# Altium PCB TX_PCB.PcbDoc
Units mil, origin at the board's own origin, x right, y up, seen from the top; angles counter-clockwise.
Board outline 2335 x 1875 mil, 2 copper layers (Top Layer, Bottom Layer); 103 components, 81 nets, 424 pads, 0 vias.
Unrouted connection lines stored in the file: 259.
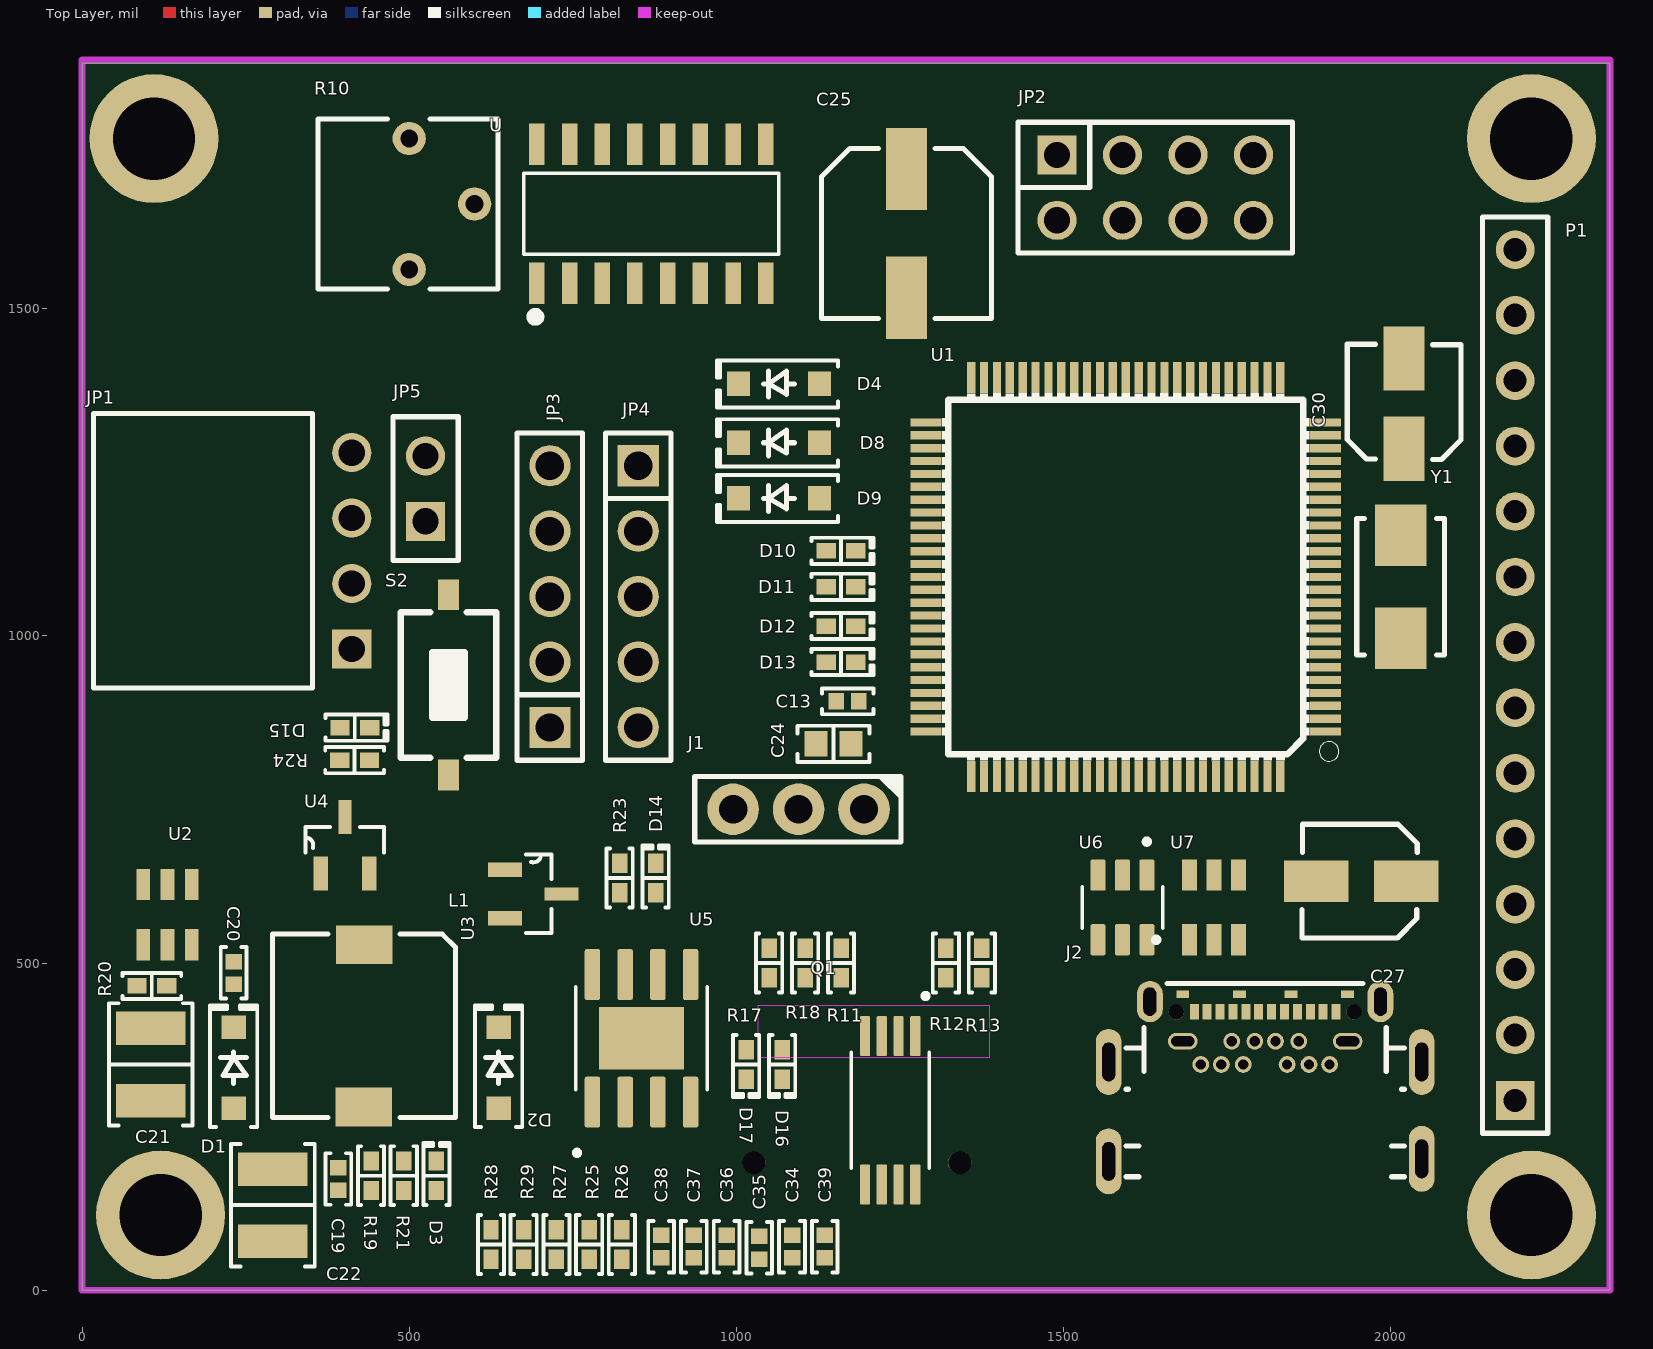
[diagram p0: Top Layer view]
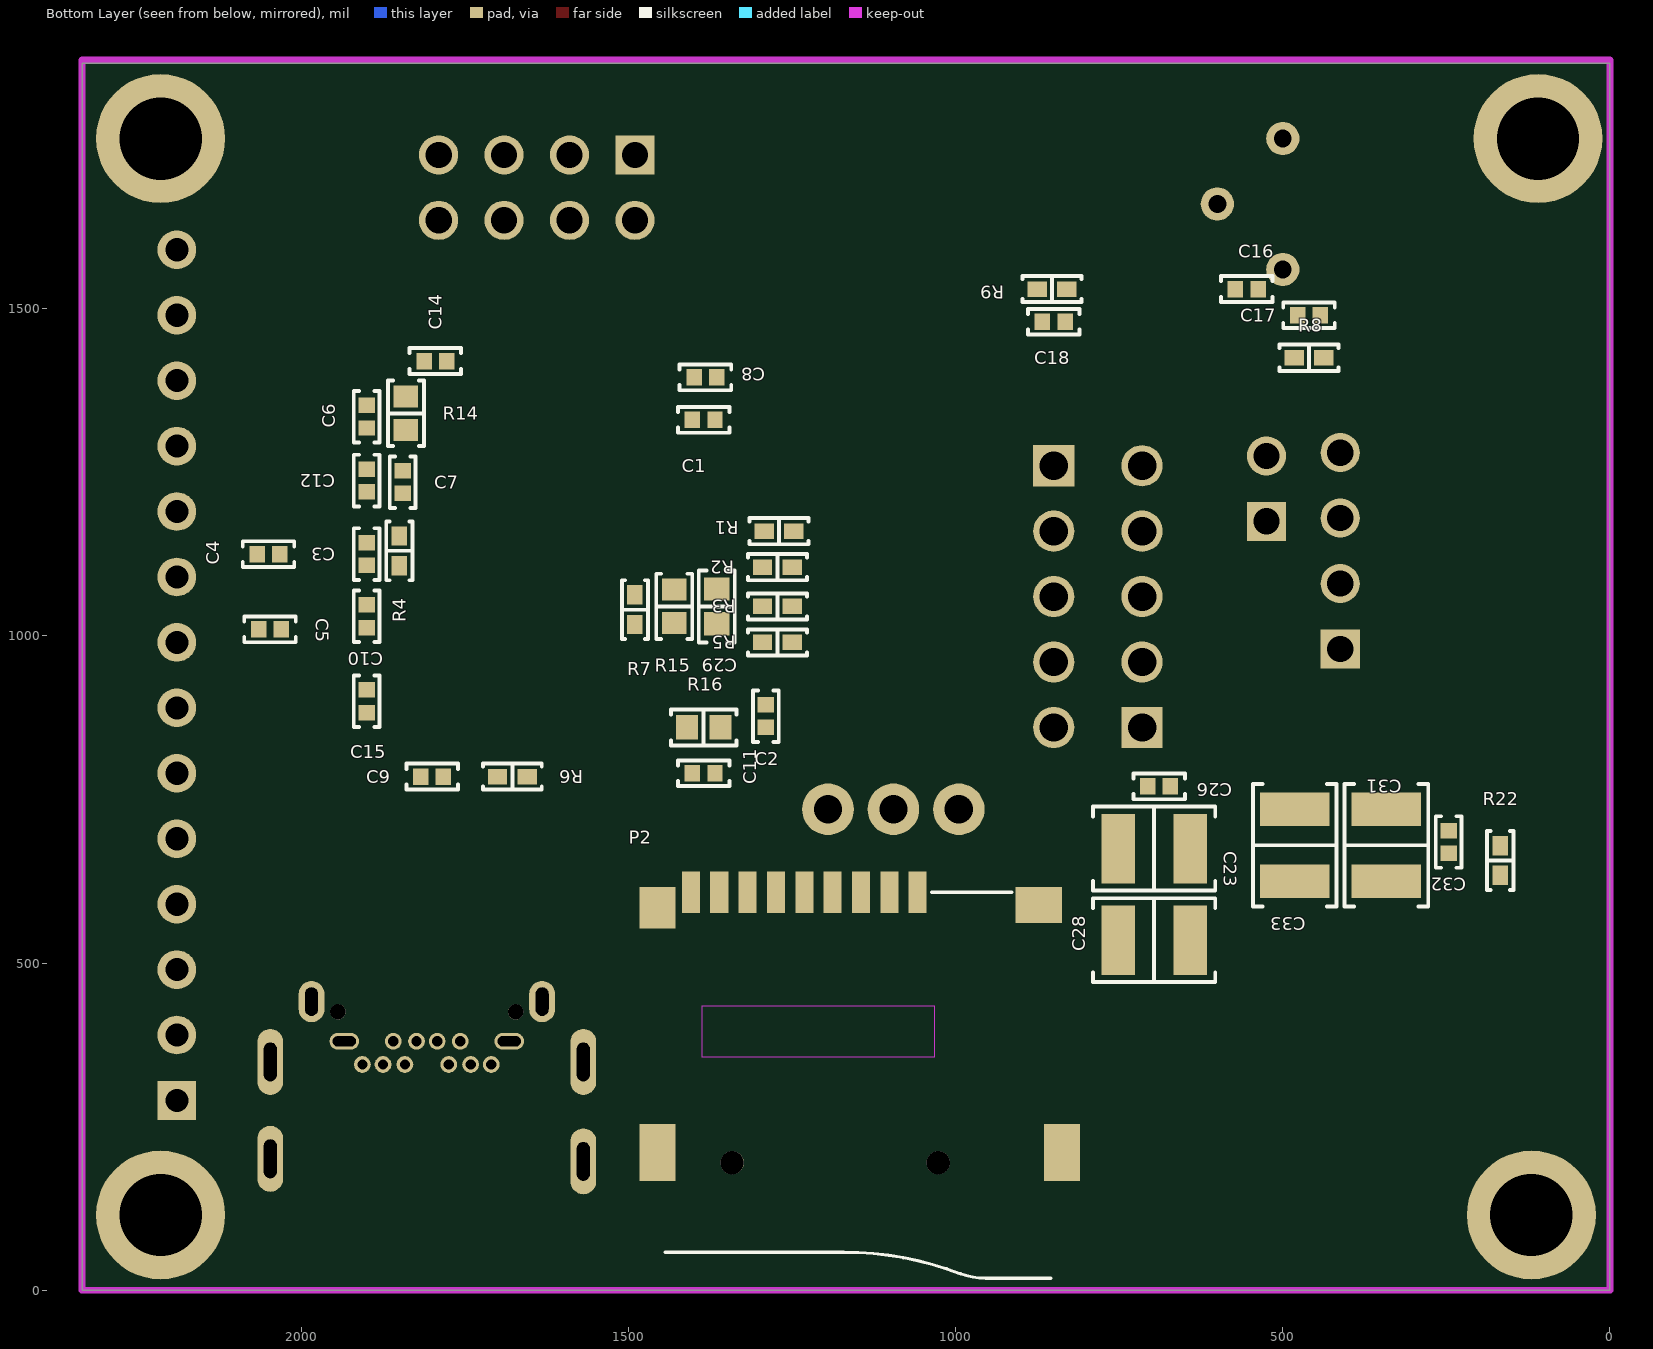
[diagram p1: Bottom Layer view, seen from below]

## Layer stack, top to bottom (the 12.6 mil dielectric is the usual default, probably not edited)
Top Solder: solder mask 0.4, Solder Resist, Dk 3.5
Top Layer: signal copper 1.4
Dielectric 1: dielectric 12.6, FR-4, Dk 4.8
Bottom Layer: signal copper 1.4
Bottom Solder: solder mask 0.4, Solder Resist, Dk 3.5

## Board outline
0,0 0,1875 2335,1875 2335,0

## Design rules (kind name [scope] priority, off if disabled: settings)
Clearance [All] p1: gap=5 ignorepadtopadclearanceinfootprint=FALSE
PolygonConnect [All] p1: connectstyle=Relief reliefconductorwidth=10 reliefentries=4 polygonreliefangle="90 Angle" airgapwidth=10
RoutingVias [All] p1: holewidth=28 width=50 viastyle="Through Hole" minholewidth=28 minwidth=50 maxholewidth=28 maxwidth=50
SolderMaskExpansion [All] p1: expansion=4 istentingtop=FALSE
Width [All] p1: maxlimit=10 minlimit=10 preferedwidth=10
30 further rules are at their usual default settings.

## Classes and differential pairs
component class USB_C: C34 C35 C36 C37 C38 C39 D16 D17 J2 Q1 R25 R26 R27 R28 R29 U5 U6 U7
component class Audio: C16 C17 C18 JP5 P2 R8 R9 R10 R11 R12 R13 R17 R18 U
component class Power_2: C19 C20 C21 C22 C23 C26 C28 C31 C32 C33 D1 D2 D3 D14 D15 L1 R19 R20 R21 R22 R23 R24 U2 U3 U4
component class MAIN_TX: "  " C1 C2 C3 C4 C5 C6 C7 C8 C9 C10 C11 C12 C13 C14 C15 C24 C25 C27 C29 C30 D4 D8 D9 D10 D11 D12 D13 J1 JP1 JP2 JP3 JP4 P1 R1 R2 R3 R4 R5 R6 R7 R14 R15 R16 S2 U1 Y1

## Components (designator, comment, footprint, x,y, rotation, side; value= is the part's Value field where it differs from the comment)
C1 "2.2 µF" "CAP 0402_1005" 1385,1330 r180 bottom
C2 "2.2 µF" "CAP 0402_1005" 1290,877.32 r90 bottom
C3 "0.1 µF" "CAP 0402_1005" 1900,1125 r270 bottom
C4 "20 pF" "CAP 0402_1005" 2050,1125 r180 bottom
C5 "20 pF" "CAP 0402_1005" 2047.68,1010 r180 bottom
C6 "0.1 µF" "CAP 0402_1005" 1900,1335 r270 bottom
C7 "0.1 µF" "CAP 0402_1005" 1845,1235 r270 bottom
C8 "0.1 µF" "CAP 0402_1005" 1382.32,1395 r180 bottom
C9 "0.1 µF" "CAP 0402_1005" 1800,785 r0 bottom
C10 "0.1 µF" "CAP 0402_1005" 1900,1030 r90 bottom
C11 "0.1 µF" "CAP 0402_1005" 1385,790 r180 bottom
C12 "0.1 µF" "CAP 0402_1005" 1900,1237.32 r270 bottom
C13 "0.1 µF" "CAP 0402_1005" 1170,900 r0 top
C14 "0.1 µF" "CAP 0402_1005" 1795,1420 r180 bottom
C15 "1 µF" "CAP 0402_1005" 1900,900 r90 bottom
C16 "0.22 µF" "CAP 0402_1005" 555,1530 r0 bottom
C17 "0.1 µF" "CAP 0402_1005" 460,1490 r180 bottom
C18 "1 µF" "CAP 0402_1005" 850,1480 r0 bottom
C19 "1000 pF" "CAP 0402_1005" 391.66,170 r90 top
C20 "0.1 µF" "CAP 0402_1005" 231.66,485 r270 top
C21 "10 µF" "CAP 1210_3225 - 1MM" 105,345 r90 top
C22 "22 µF" "CAP 1210_3225 - 1MM" 291.66,130 r90 top
C23 "10 µF" "CAP 1210_3225 - 1MM" 696.66,675 r0 bottom
C24 "0.1 µF" "CAP 0603_1608" 1148.43,835 r180 top
C25 "220 µF" "CAP ALSMD 6.6MM H6.1MM" 1260,1615 r270 top
C26 "0.1µF" "CAP 0402_1005" 688.98,770 r0 bottom
C27 "1 µF" "CAP ALSMD 4.3MM H5.4MM" 1955,625 r180 top
C28 "10 µF" "CAP 1210_3225 - 1MM" 696.66,535 r180 bottom
C29 "0.1 µF" "CAP 0603_1608" 1365,1045 r270 bottom
C30 "1 µF" "CAP ALSMD 4.3MM H5.4MM" 2020,1355 r90 top
C31 "10 µF" "CAP 1210_3225 - 1MM" 341.66,680 r90 bottom
C32 "0.1µF" "CAP 0402_1005" 246.66,685 r90 bottom
C33 "10 µF" "CAP 1210_3225 - 1MM" 481.66,680 r270 bottom
C34 "0.1 µF" "CAP 0402_1005" 1085,66.66 r90 top
C35 "0.1 µF" "CAP 0402_1005" 1035,65 r90 top
C36 "0.1 µF" "CAP 0402_1005" 985,66.66 r90 top
C37 "0.1 µF" "CAP 0402_1005" 935,66.66 r90 top
C38 "10 µF" "CAP 0402_1005" 885,66.66 r90 top
C39 "0.1 µF" "CAP 0402_1005" 1135,66.66 r90 top
D1 "1N5819HW-7-F" SOD-123 231.66,340 r90 top
D2 "1N5819HW-7-F" SOD-123 636.66,340 r90 top
D3 "Green" "LED 0402_1005 GREEN" 541.66,175 r90 top
D4 "1N5819HW-7-F" SOD-123 1065,1385 r180 top
D8 "1N5819HW-7-F" SOD-123 1065,1295 r180 top
D9 "1N5819HW-7-F" SOD-123 1065,1210 r180 top
D10 "Red" "LED 0402_1005 RED" 1160,1130 r0 top
D11 "Yellow" "LED 0402_1005 YELLOW" 1160,1075 r0 top
D12 "Green" "LED 0402_1005 GREEN" 1160,1015 r0 top
D13 "Blue" "LED 0402_1005 BLUE" 1160,960 r0 top
D14 "Yellow" "LED 0402_1005 YELLOW" 876.66,630 r90 top
D15 "Red" "LED 0402_1005 RED" 416.87,859.76 r0 top
D16 "Green" "LED 0402_1005 GREEN" 1070,345 r270 top
D17 "Red" "LED 0402_1005 RED" 1015,345 r270 top
J1 "M20-7820342" "HARWIN M20-7820345" 1095,735 r270 top
J2 "2129691-1" "TE USB-C 2129691-1" 1808.07,248.15 r180 top
JP1 "JP 1x4 2.54" "JP 1x4 CC" 412.32,1130 r90 top
JP2 "JP 2x4 2.54" "JP 2x4 CT" 1640,1685 r0 top
JP3 "JP 1x5 2.54" "JP 1x5 DT" 715,860 r90 top
JP4 "JP 1x5 2.54" "JP 1x5 DT" 850,1260 r270 top
JP5 "JP 1x2 2.54" "JP 1x2 CT" 525,1175 r90 top
L1 "10µH" "TDK SLF7032" 430.93,403.98 r270 top
P1 "Header 14" HDR1X14 2190,290 r90 top
P2 "ST-TF-003A" SUNTECH_ST-TF-003A 1196.61,398.39 r180 bottom
Q1 "FS8205A" SOP65P640X120-8N 1235,275 r270 top
R1 "680 Ohms" "RES 0402_1005" 1270,1160 r180 bottom
R2 "680 Ohms" "RES 0402_1005" 1272.36,1105 r180 bottom
R3 "680 Ohms" "RES 0402_1005" 1272.36,1045 r180 bottom
R4 "100 kOhms" "RES 0402_1005" 1850,1130 r90 bottom
R5 "680 Ohms" "RES 0402_1005" 1272.36,990 r180 bottom
R6 "10 kOhms" "RES 0402_1005" 1677.36,785 r0 bottom
R7 "10 kOhms" "RES 0402_1005" 1490,1040 r90 bottom
R8 "4.7 kOhms" "RES 0402_1005" 460,1425 r0 bottom
R9 "10 kOhms" "RES 0402_1005" 852.64,1530 r0 bottom
R10 "10 kOhms" "BOURNS TRIMPOT 3362P-1" 510,1660 r270 top
R11 "4.7 kOhms" "RES 0402_1005" 1160,500 r90 top
R12 "4.7 kOhms" "RES 0402_1005" 1320,500 r270 top
R13 "4.7 kOhms" "RES 0402_1005" 1375,500 r270 top
R14 "47 Ohms" "RES 0603_1608" 1840,1340 r270 bottom
R15 "20 kOhms" "RES 0603_1608" 1430,1045 r270 bottom
R16 "0 Ohms" "RES 0603_1608" 1385,860 r0 bottom
R17 "4.7 kOhms" "RES 0402_1005" 1050,500 r270 top
R18 "4.7 kOhms" "RES 0402_1005" 1105,500 r270 top
R19 "52.3 kOhms" "RES 0402_1005" 441.66,175 r90 top
R20 "100 kOhms" "RES 0402_1005" 106.66,465 r0 top
R21 "1 kOhms" "RES 0402_1005" 491.66,175 r90 top
R22 "10 kOhms" "RES 0402_1005" 167.72,656.65 r270 bottom
R23 "680 Ohms" "RES 0402_1005" 821.66,630 r90 top
R24 "680 Ohms" "RES 0402_1005" 416.66,810 r0 top
R25 "1.2 kOhms" "RES 0402_1005" 775,70 r90 top
R26 "1 kOhms" "RES 0402_1005" 825,70 r90 top
R27 "110 Ohms" "RES 0402_1005" 725,70 r90 top
R28 "1 kOhms" "RES 0402_1005" 625,70 r90 top
R29 "1 kOhms" "RES 0402_1005" 675,70 r90 top
S2 "SW-SMD" SW-SMD 560,925 r270 top
U "PAM8403DR" SOIC127P605X150-16N 870,1645 r90 top
U1 "MCU-STM32F407VET6(LQFP100)" LQFP100-0.5-13.8X13.8MM 1595,1090 r180 top
U2 "LM2734YMK" SOT95P285X100-6N 130.72,574 r270 top
U3 "MCP1700T-3302E/TT" SOT95P237X112-3N 689.66,605.71 r0 top
U4 "MCP1700T-3302E/TT" SOT95P237X112-3N 401.66,680 r90 top
U5 "TP4056" SOP127P600X175-9N 855,385 r90 top
U6 "USBLC6-2SC6" SOT95P280X145-6N#1 1590,585 r270 top
U7 "DW01A" SOT95P280X145-6N#2 1730,585 r90 top
Y1 "8 MHz" "NDK NX5032GA" 2015,1075 r270 top

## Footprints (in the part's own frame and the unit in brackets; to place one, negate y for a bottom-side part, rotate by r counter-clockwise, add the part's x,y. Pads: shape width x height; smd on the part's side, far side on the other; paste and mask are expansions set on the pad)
"BOURNS TRIMPOT 3362P-1" [mm] "3362 -1/4 ? Square Trimpot® Trimming Potentiometer"
  round 1.29 hole 0.69: 1(-2.54,-0.254) 2(0,2.286) 3(2.54,-0.254)
  silkscreen extent -3.3,-3.79 3.3,3.2, body extent -3.3,-3.79 3.3,3.2, height 4.7
"CAP 0402_1005" [mm] "Chip Capacitor, 2-Leads, Body 1.02x0.51mm, IPC Medium Density"
  rect 0.6x0.64 smd: 1(-0.44,0) 2(0.44,0)
  silkscreen extent -1,-0.5 1,0.5, body extent -0.5,-0.26 0.5,0.26, height 0.52
"CAP 0603_1608" [mm] "Chip Capacitor, 2-Leads, Body 1.60x0.80mm, IPC Medium Density"
  rect 0.9x1 smd: 1(-0.675,0) 2(0.675,0)
  silkscreen extent -1.4,-0.7 1.4,0.7, body extent -0.8,-0.41 0.8,0.41, height 0.82
"CAP 1210_3225 - 1MM" [mm] "Chip Capacitor, 2-Leads, Body 3.20x2.50mm, IPC Medium Density"
  rect 1.3x2.7 smd: 1(-1.4,0) 2(1.4,0)
  silkscreen extent -2.38,-1.62 2.38,1.62, body extent -1.6,-1.25 1.6,1.25, height 1
"CAP ALSMD 4.3MM H5.4MM" [mm] "Aluminum Electrolytic Capacitor, Body 4.30x4.30x5.40mm, IPC Low Density"
  rect 2.5x1.6 smd: 1(-1.75,0) 2(1.75,0)
  silkscreen extent -2.17,-2.21 2.3,2.2, body extent -2.3,-2.2 2.3,2.2, height 5.4
"CAP ALSMD 6.6MM H6.1MM" [mm] "Aluminum Electrolytic Capacitor, Body 6.60x6.60x6.10mm, IPC Low Density"
  rect 3.2x1.6 smd: 1(-2.5,0) 2(2.5,0)
  silkscreen extent -3.3,-3.3 3.3,3.3, body extent -3.5,-3.3 3.5,3.3, height 6.1
"HARWIN M20-7820345" [mm] "2.54mm DIL PC TAIL PIN HEADER ASSEMBLY"
  round 2 hole 1.1: 1(0,2.54) 2(0,0) 3(0,-2.54)
  silkscreen extent -1.27,-4.03 1.27,4, body extent -1.25,-4.01 1.25,4.01, height 8.5
HDR1X14 [mm] "Connector; Header; 14 Position"
  rect 1.5x1.5 hole 0.9: 1(0,0)
  round 1.5 hole 0.9: 2(2.54,0) 3(5.08,0) 4(7.62,0) 5(10.16,0) 6(12.7,0) 7(15.24,0) 8(17.78,0) 9(20.32,0) 10(22.86,0) 11(25.4,0) 12(27.94,0) 13(30.48,0) 14(33.02,0)
  silkscreen extent -1.27,-1.27 34.29,1.27, body extent -1.27,-1.27 34.29,1.27, height 7
"JP 1x2 CT" [mm] "JP 1x2 CT"
  rect 1.52x1.52 hole 1.02: 1(0,0)
  round 1.52 hole 1.02: 2(2.54,0)
  silkscreen extent -1.52,-1.27 4.06,1.27, body extent -1.52,-1.25 4.06,1.25, height 8.51
"JP 1x4 CC" [mm] "4 pins, 1 row, straight, gold plating"
  rect 1.52x1.52 hole 1.02: 1(-3.81,0)
  round 1.52 hole 1.02: 2(-1.27,0) 3(1.27,0) 4(3.81,0)
  silkscreen extent -5.33,1.52 5.33,10.03, body extent -5.33,-0.25 5.33,10.05, height 2.51
"JP 1x5 DT" [mm] "5 pins, 1 row, straight, gold plating"
  rect 1.6x1.6 hole 1.1: 1(0,0)
  round 1.6 hole 1.1: 2(2.54,0) 3(5.08,0) 4(7.62,0) 5(10.16,0)
  silkscreen extent -1.27,-1.27 11.43,1.27, body extent -1.27,-1.27 11.43,1.27, height 8.54
"JP 2x4 CT" [mm] "8 pins, dual row, straight, gold plating"
  rect 1.52x1.52 hole 1.02: 1(-3.81,1.27)
  round 1.52 hole 1.02: 2(-1.27,1.27) 3(1.27,1.27) 4(3.81,1.27) 5(3.81,-1.27) 6(1.27,-1.27) 7(-1.27,-1.27) 8(-3.81,-1.27)
  silkscreen extent -5.33,-2.54 5.33,2.54, body extent -5.33,-2.54 5.33,2.54, height 8.51
"LED 0402_1005 BLUE" [mm] "Chip Diode, 2-Leads, Body 1.00x0.50mm, IPC Medium Density"
  rect 0.75x0.6 smd: 1(-0.575,0) 2(0.575,0)
  silkscreen extent -1.14,-0.51 1.27,0.51, body extent -0.5,-0.25 0.5,0.25, height 0.21
"LED 0402_1005 GREEN" [mm] "Chip Diode, 2-Leads, Body 1.00x0.50mm, IPC Medium Density"
  rect 0.75x0.6 smd: 1(-0.575,0) 2(0.575,0)
  silkscreen extent -1.14,-0.51 1.27,0.51, body extent -0.5,-0.25 0.5,0.25, height 0.21
"LED 0402_1005 RED" [mm] "Chip Diode, 2-Leads, Body 1.00x0.50mm, IPC Medium Density"
  rect 0.75x0.6 smd: 1(-0.575,0) 2(0.575,0)
  silkscreen extent -1.14,-0.51 1.27,0.51, body extent -0.5,-0.25 0.5,0.25, height 0.21
"LED 0402_1005 YELLOW" [mm] "Chip Diode, 2-Leads, Body 1.00x0.50mm, IPC Medium Density"
  rect 0.75x0.6 smd: 1(-0.575,0) 2(0.575,0)
  silkscreen extent -1.14,-0.51 1.27,0.51, body extent -0.5,-0.25 0.5,0.25, height 0.21
LQFP100-0.5-13.8X13.8MM [mm]
  rect 1.2x0.32 smd: 1(-7.75,6) 2(-7.75,5.5) 3(-7.75,5) 4(-7.75,4.5) 5(-7.75,4) 6(-7.75,3.5) 7(-7.75,3) 8(-7.75,2.5) 9(-7.75,2) 10(-7.75,1.5) 11(-7.75,1) 12(-7.75,0.5) 13(-7.75,0) 14(-7.75,-0.5) 15(-7.75,-1) 16(-7.75,-1.5) 17(-7.75,-2) 18(-7.75,-2.5) 19(-7.75,-3) 20(-7.75,-3.5) 21(-7.75,-4) 22(-7.75,-4.5) 23(-7.75,-5) 24(-7.75,-5.5) 25(-7.75,-6) 51(7.75,-6) 52(7.75,-5.5) 53(7.75,-5) 54(7.75,-4.5) 55(7.75,-4) 56(7.75,-3.5) 57(7.75,-3) 58(7.75,-2.5) 59(7.75,-2) 60(7.75,-1.5) 61(7.75,-1) 62(7.75,-0.5) 63(7.75,0) 64(7.75,0.5) 65(7.75,1) 66(7.75,1.5) 67(7.75,2) 68(7.75,2.5) 69(7.75,3) 70(7.75,3.5) 71(7.75,4) 72(7.75,4.5) 73(7.75,5) 74(7.75,5.5) 75(7.75,6)
  rect 0.32x1.2 smd: 26(-6,-7.75) 27(-5.5,-7.75) 28(-5,-7.75) 29(-4.5,-7.75) 30(-4,-7.75) 31(-3.5,-7.75) 32(-3,-7.75) 33(-2.5,-7.75) 34(-2,-7.75) 35(-1.5,-7.75) 36(-1,-7.75) 37(-0.5,-7.75) 38(0,-7.75) 39(0.5,-7.75) 40(1,-7.75) 41(1.5,-7.75) 42(2,-7.75) 43(2.5,-7.75) 44(3,-7.75) 45(3.5,-7.75) 46(4,-7.75) 47(4.5,-7.75) 48(5,-7.75) 49(5.5,-7.75) 50(6,-7.75) 76(6,7.75) 77(5.5,7.75) 78(5,7.75) 79(4.5,7.75) 80(4,7.75) 81(3.5,7.75) 82(3,7.75) 83(2.5,7.75) 84(2,7.75) 85(1.5,7.75) 86(1,7.75) 87(0.5,7.75) 88(0,7.75) 89(-0.5,7.75) 90(-1,7.75) 91(-1.5,7.75) 92(-2,7.75) 93(-2.5,7.75) 94(-3,7.75) 95(-3.5,7.75) 96(-4,7.75) 97(-4.5,7.75) 98(-5,7.75) 99(-5.5,7.75) 100(-6,7.75)
  silkscreen extent -8.27,-7.13 7.11,7.15, body extent -8,-8 8,8, height 1.6
"NDK NX5032GA" [mm] "Crystal, 2-Leads, Body 5.00x3.20mm, IPC Medium Density"
  rect 2.4x2 smd: 1(-2,0) 2(2,0)
  silkscreen extent -2.65,-1.7 2.65,1.7, body extent -2.5,-1.6 2.5,1.6, height 1.2
"RES 0402_1005" [mm] "Chip Resistor, 2-Leads, Body 1.0x0.5mm, IPC Medium Density"
  rect 0.75x0.6 smd: 1(-0.575,0) 2(0.575,0)
  silkscreen extent -1.14,-0.51 1.14,0.51, body extent -0.5,-0.25 0.5,0.25, height 0.35
"RES 0603_1608" [mm] "Chip Resistor, 2-Leads, Body 1.60x0.80mm, IPC Medium Density"
  rect 0.85x0.95 smd: 1(-0.65,0) 2(0.65,0)
  silkscreen extent -1.27,-0.7 1.27,0.7, body extent -0.8,-0.4 0.8,0.4, height 0.45
SOD-123 [mm] "SOD, 2-Leads, Body 1.55x3.70mm, IPC Medium Density"
  rect 0.9x0.95 smd: 1(-1.575,0) 2(1.575,0)
  silkscreen extent -2.3,-0.92 2.41,0.92, body extent -1.86,-0.78 1.86,0.77, height 1.35
SOIC127P605X150-16N [mm]
  rect 1.6x0.6 smd: 1(-2.7,4.445) 2(-2.7,3.175) 3(-2.7,1.905) 4(-2.7,0.635) 5(-2.7,-0.635) 6(-2.7,-1.905) 7(-2.7,-3.175) 8(-2.7,-4.445) 9(2.7,-4.445) 10(2.7,-3.175) 11(2.7,-1.905) 12(2.7,-0.635) 13(2.7,0.635) 14(2.7,1.905) 15(2.7,3.175) 16(2.7,4.445)
  silkscreen extent -4.14,-4.95 1.58,4.95
SOP65P640X120-8N [mm]
  rrect25% 1.56x0.4 smd: 1(-2.88,0.975) 2(-2.88,0.325) 3(-2.88,-0.325) 4(-2.88,-0.975) 5(2.88,-0.975) 6(2.88,-0.325) 7(2.88,0.325) 8(2.88,0.975)
  silkscreen extent -4.54,-1.52 2.25,1.52, body extent -1.47,-3.2 1.47,3.2, height 1.2
SOP127P600X175-9N [mm]
  rrect25% 1.97x0.6 smd: 1(-2.475,1.905) 2(-2.475,0.635) 3(-2.475,-0.635) 4(-2.475,-1.905) 5(2.475,-1.905) 6(2.475,-0.635) 7(2.475,0.635) 8(2.475,1.905)
  rect 2.413x3.302 smd paste-3: 9(0,0)
  silkscreen extent -4.54,-2.55 2,2.6, body extent -3,-2.45 3,2.45, height 1.75
SOT95P237X112-3N [mil]
  rect 52x22 smd: 1(-43,37) 2(-43,-37)
  rect 52x20 smd: 3(43,0)
  silkscreen extent -11,-60 28,60
SOT95P280X145-6N#1 [mm]
  rrect25% 1.21x0.59 smd: 1(-1.255,0.95) 2(-1.255,0) 3(-1.255,-0.95) 4(1.255,-0.95) 5(1.255,0) 6(1.255,0.95)
  silkscreen extent -2.65,-1.56 0.81,1.56, body extent -1.4,-1.46 1.4,1.46, height 0.4
SOT95P280X145-6N#2 [mm]
  rect 1.21x0.59 smd: 1(-1.255,0.95) 2(-1.255,0) 3(-1.255,-0.95) 4(1.255,-0.95) 5(1.255,0) 6(1.255,0.95)
  silkscreen extent -1.35,2.14 -1.16,2.34, body extent -1.4,-1.45 1.4,1.45, height 1.45
SOT95P285X100-6N [mil]
  rect 48x21 smd: 1(-46,37) 2(-46,0) 3(-46,-37) 4(46,-37) 5(46,0) 6(46,37)
SUNTECH_ST-TF-003A [mm]
  rect 0.7x1.6 smd: 1(3.52,5.33) 2(2.42,5.33) 3(1.32,5.33) 4(0.22,5.33) 5(-0.88,5.33) 6(-1.98,5.33) 7(-3.08,5.33) 8(-4.18,5.33) 9(-5.28,5.33)
  rect 1.4x1.6 smd: G1(-6.58,4.73)
  rect 1.4x2.2 smd: G2(-6.58,-4.77) G3(9.12,-4.77)
  rect 1.8x1.4 smd: G4(8.22,4.83)
  round 0.9 hole 0.9 unplated: ""(-3.68,-5.17) ""(4.32,-5.17)
  Keep-Out Layer region: 4.172,-1.073 -4.833,-1.073 -4.833,0.928 4.172,0.928
  silkscreen extent -6.29,-9.66 8.7,5.33
SW-SMD [mm] "Switch SMD type"
  rect 1.2x0.8 smd: 1(-3.5,0) 2(3.5,0)
  silkscreen extent -2.82,-1.85 2.82,1.85, body extent -3.05,-1.85 3.05,1.85, height 2.5
"TDK SLF7032" [mm] "Power Inductor, 2-Leads, TDK, SLF7032T-221MR29-2PF"
  rect 1.5x2.2 smd: 1(-3.15,0.013) 2(3.15,-0.013)
  silkscreen extent -3.56,-3.55 3.56,3.55, body extent -3.56,-3.56 3.56,3.54, height 3.39
"TE USB-C 2129691-1" [mm]
  rect 0.35x0.6 smd: A1(2.75,-4.5) A2(2.25,-4.5) A3(1.75,-4.5) A4(1.25,-4.5) A5(0.75,-4.5) A6(0.25,-4.5) A7(-0.25,-4.5) A8(-0.75,-4.5) A9(-1.25,-4.5) A10(-1.75,-4.5) A11(-2.25,-4.5) A12(-2.75,-4.5)
  oval 1.15x0.65 hole 0.4 slot 0.9 at 0 deg: B1(-3.2,-3.36) B12(3.2,-3.36)
  round 0.65 hole 0.4: B2(-2.5,-2.46) B3(-1.7,-2.46) B4(-1.3,-3.36) B5(-0.85,-2.46) B6(-0.4,-3.36) B7(0.4,-3.36) B8(0.85,-2.46) B9(1.3,-3.36) B10(1.7,-2.46) B11(2.5,-2.46)
  round 0.6 hole 0.6 unplated mask+0.102: M(-3.45,-4.5) M(3.45,-4.5)
  oval 1x2.56 hole 0.5 slot 1.5 at 90 deg: S(-6.075,-2.56) S(-6.075,1.2) S(6.075,-2.56) S(6.075,1.3)
  oval 1x1.6 hole 0.5 slot 1.1 at 90 deg: S(-4.475,-4.9) S(4.475,-4.9)
  rect 0.5x0.3 smd: S(-3.2,-5.19) S(-1,-5.19) S(1,-5.19) S(3.2,-5.19)
  silkscreen extent -5.4,-5.6 5.4,1.9, body extent -6.18,-5.3 6.18,5.4, height 2.27

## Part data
C1 C2: library part GRT155C81A225KE13D, "CAP CER 2.2UF 10V X6S 0402", Device Package="0402 (1005 Metric)", Manufacturer="Murata Electronics", Operating Temperature="-55°C ~ 105°C", Ratings=AEC-Q200, Supplier Part Number 1=490-12239-1-ND, Temperature Coefficient=X6S, Tolerance=±10%, Voltage - Rated=10V
C3 C6 C7 C8 C9 C10 C11 C12 C13 C14 C20: library part KGM05AR51A104KN, "CAP CER 0.1UF 10V X5R 0402", Device Package="0402 (1005 Metric)", Manufacturer="KYOCERA AVX", Operating Temperature="-55°C ~ 85°C", Supplier Part Number 1=478-KGM05AR51A104KNCT-ND, Temperature Coefficient=X5R, Tolerance=±10%, Voltage - Rated=10V
C4 C5: library part C0402C200K8GAC7867, "CAP CER 20PF 10V NP0 0402", Device Package="0402 (1005 Metric)", Manufacturer=KEMET, Operating Temperature="-55°C ~ 125°C", Supplier Part Number 1=399-14429-1-ND, Temperature Coefficient="C0G, NP0", Tolerance=±10%, Voltage - Rated=10V
C15: library part GRM155C71A105KE11D, "CAP CER 1UF 10V X7S 0402", Device Package="0402 (1005 Metric)", Manufacturer="Murata Electronics", Operating Temperature="-55°C ~ 125°C", Supplier Part Number 1=490-14457-1-ND, Temperature Coefficient=X7S, Tolerance=±10%, Voltage - Rated=10V
C16: library part 0402X224K100CT, "CAP CER 0.22UF 10V X5R 0402", Device Package="0402 (1005 Metric)", Manufacturer="Walsin Technology Corporation", Operating Temperature="-55°C ~ 85°C", Supplier Part Number 1=1292-1370-1-ND, Temperature Coefficient=X5R, Tolerance=±10%, Voltage - Rated=10V
C17: library part CGA2B2X5R1A104M050BA, "CAP CER 0.1UF 10V X5R 0402", Device Package="0402 (1005 Metric)", Manufacturer="TDK Corporation", Operating Temperature="-55°C ~ 85°C", Ratings=AEC-Q200, Supplier Part Number 1=445-12157-1-ND, Temperature Coefficient=X5R, Tolerance=±20%, Voltage - Rated=10V
C18: library part C0402C105K8PAC7867, "CAP CER 1UF 10V X5R 0402", Device Package="0402 (1005 Metric)", Manufacturer=KEMET, Operating Temperature="-55°C ~ 85°C", Supplier Part Number 1=399-C0402C105K8PAC7867CT-ND, Temperature Coefficient=X5R, Tolerance=±10%, Voltage - Rated=10V
C19: library part LMF105B7102MVHF, "CAP CER 1000PF 10V X7R 0402", Device Package="0402 (1005 Metric)", Manufacturer="Taiyo Yuden", Operating Temperature="-55°C ~ 125°C", Ratings=AEC-Q200, Supplier Part Number 1=587-LMF105B7102MVHFCT-ND, Temperature Coefficient=X7R, Tolerance=±20%, Voltage - Rated=10V
C21 C23 C28 C31 C33: library part CGA6P3X8R1C106M250AB, "CAP CER 10UF 16V X8R 1210", Device Package="1210 (3225 Metric)", Manufacturer="TDK Corporation", Operating Temperature="-55°C ~ 150°C", Ratings=AEC-Q200, Supplier Part Number 1=445-13057-1-ND, Temperature Coefficient=X8R, Tolerance=±20%, Voltage - Rated=16V
C22: library part C1210C226K4RAC7800, "CAP CER 22UF 16V X7R 1210", Device Package="1210 (3225 Metric)", Manufacturer=KEMET, Operating Temperature="-55°C ~ 125°C", Supplier Part Number 1=399-11662-1-ND, Temperature Coefficient=X7R, Tolerance=±10%, Voltage - Rated=16V
C24 C29: library part VJ0603Y104KXQCW1BC, "CAP CER 0.1UF 10V X7R 0603", Device Package="0603 (1608 Metric)", Manufacturer="Vishay Vitramon", Operating Temperature="-55°C ~ 125°C", Supplier Part Number 1=720-1689-1-ND, Temperature Coefficient=X7R, Tolerance=±10%, Voltage - Rated=10V
C25: library part UCM1A221MCL1GS, "CAP ALUM 220UF 20% 10V SMD", Device Package="Radial, Can - SMD", Lifetime @ Temp.="2000 Hrs @ 105°C", Manufacturer=Nichicon, Operating Temperature="-55°C ~ 105°C", Ratings=AEC-Q200, Ripple Current @ High Frequency="300 mA @ 100 kHz", Ripple Current @ Low Frequency="150 mA @ 120 Hz", Supplier Part Number 1=493-17470-1-ND, Tolerance=±20%, Voltage - Rated="10 V"
C26 C32: library part 0402ZC104KAT2A, "CAP CER 0.1UF 10V X7R 0402", Device Package="0402 (1005 Metric)", Manufacturer="AVX Corporation", Operating Temperature="-55°C ~ 125°C", Supplier Part Number 1=478-7891-1-ND, Temperature Coefficient=X7R, Tolerance=±10%, Voltage - Rated=10V
C27 C30: library part EEE-HD1H1R0R, "CAP ALUM 1UF 20% 50V SMD", Device Package="Radial, Can - SMD", Lifetime @ Temp.="5000 Hrs @ 105°C", Manufacturer="Panasonic Electronic Components", Operating Temperature="-40°C ~ 105°C", Ratings=AEC-Q200, Ripple Current @ High Frequency="11.9 mA @ 10 kHz", Ripple Current @ Low Frequency="7 mA @ 120 Hz", Supplier Part Number 1=PCE4972CT-ND, Tolerance=±20%, Voltage - Rated="50 V"
C34 C35 C36 C37 C39: library part KGM05AR71A104KH, "CAP CER 0.1UF 10V X7R 0402", Device Package="0402 (1005 Metric)", Manufacturer="KYOCERA AVX", Operating Temperature="-55°C ~ 125°C", Supplier Part Number 1=478-KGM05AR71A104KHCT-ND, Temperature Coefficient=X7R, Tolerance=±10%, Voltage - Rated=10V
C38: library part CL05A106MP8NUB8, "CAP CER 10UF 10V X5R 0402", Device Package="0402 (1005 Metric)", Manufacturer="Samsung Electro-Mechanics", Operating Temperature="-55°C ~ 85°C", Supplier Part Number 1=1276-6830-1-ND, Temperature Coefficient=X5R, Tolerance=±20%, Voltage - Rated=10V
D1 D2 D4 D8 D9: "DIODE SCHOTTKY 40V 1A SOD123", Capacitance @ Vr, F="60pF @ 4V, 1MHz", Current - Average Rectified (Io)=1A, Current - Reverse Leakage @ Vr="1 mA @ 40 V", Manufacturer="Diodes Incorporated", Operating Temperature - Junction="-65°C ~ 125°C", Package / Case=SOD-123, Supplier Part Number 1=1N5819HW-FDICT-ND, Voltage - DC Reverse (Vr) (Max)="40 V", Voltage - Forward (Vf) (Max) @ If="450 mV @ 1 A"
D3: library part QBLP595-AG15-2897, "LED GREEN CLEAR 0402 SMD", Current - Test=5mA, Device Package="0402 (1005 Metric)", Lens Color=Colorless, Manufacturer="QT Brightek (QTB)", Millicandela Rating=16.5mcd, Supplier Device Package=0402, Supplier Part Number 1=1516-QBLP595-AG15-2897CT-ND, Voltage - Forward (Vf) (Typ)=1.9V
D10: library part SM0402RC, "LED RED CLEAR 0402 SMD", Current - Test=20mA, Device Package="0402 (1005 Metric)", Lens Color=Colorless, Manufacturer="Bivar Inc.", Millicandela Rating=90mcd, Supplier Device Package=0402, Supplier Part Number 1=492-2208-1-ND, Voltage - Forward (Vf) (Typ)=2.1V
D11: library part IN-S42ATY, "LED YELLOW CLEAR 0402 SMD", Current - Test=20mA, Device Package="0402 (1005 Metric)", Lens Color=Clear, Manufacturer=Inolux, Millicandela Rating=145mcd, Supplier Device Package=0402, Supplier Part Number 1=1830-1059-1-ND, Voltage - Forward (Vf) (Typ)=1.9V
D12: library part APG1005ZGC-5MAV, "LED GREEN CLEAR 0402 SMD", Current - Test=5mA, Device Package="0402 (1005 Metric)", Lens Color=Colorless, Manufacturer=Kingbright, Millicandela Rating=280mcd, Supplier Device Package=0402, Supplier Part Number 1=754-APG1005ZGC-5MAVCT-ND, Voltage - Forward (Vf) (Typ)=2.85V
D13: library part XZBBR68W5MAV-3, "LED BLUE CLEAR 0402 SMD", Current - Test=5mA, Device Package="0402 (1005 Metric)", Lens Color=Colorless, Manufacturer=SunLED, Millicandela Rating=27mcd, Supplier Device Package=0402, Supplier Part Number 1=1497-1388-1-ND, Voltage - Forward (Vf) (Typ)=2.9V
D14: library part IN-S42BT5Y, "LED YELLOW CLEAR 0402 SMD", Current - Test=5mA, Device Package="0402 (1005 Metric)", Lens Color=0.50mm, Manufacturer=Inolux, Millicandela Rating=23mcd, Supplier Device Package=0402, Supplier Part Number 1=1830-IN-S42BT5YCT-ND, Voltage - Forward (Vf) (Typ)=2V
D15: library part QBLP595-R5, "LED RED CLEAR 0402 SMD", Current - Test=5mA, Device Package="0402 (1005 Metric)", Lens Color=Colorless, Manufacturer="QT Brightek (QTB)", Millicandela Rating=31.5mcd, Supplier Device Package=0402, Supplier Part Number 1=1516-QBLP595-R5CT-ND, Voltage - Forward (Vf) (Typ)=1.85V
D16: library part 150040GS73240, "LED GREEN CLEAR 0402 SMD", Current - Test=20mA, Device Package="0402 (1005 Metric)", Lens Color=Colorless, Manufacturer="Würth Elektronik", Millicandela Rating=800mcd, Supplier Part Number 1=732-11990-1-ND, Voltage - Forward (Vf) (Typ)=3.2V
D17: library part 150040SS73220, "LED RED CLEAR 0402 SMD", Current - Test=20mA, Device Package="0402 (1005 Metric)", Lens Color=Colorless, Manufacturer="Würth Elektronik", Millicandela Rating=90mcd, Supplier Device Package=0402, Supplier Part Number 1=732-13421-1-ND, Voltage - Forward (Vf) (Typ)=2V
J1: "CONN RCPT 3POS 0.1 GOLD PCB", Current Rating (Amps)=3A, Insulation Color=Black, Manufacturer="Harwin Inc.", Material Flammability Rating="UL94 V-0", Operating Temperature="-40°C ~ 105°C", Supplier Part Number 1=952-1783-ND
J2: "CONN RCPT USB3.1 TYPEC 24POS SMD", Current Rating (Amps)="0.25A, 1.25A, 5A", Manufacturer="TE Connectivity AMP Connectors", Operating Temperature="-30°C ~ 85°C", Supplier Part Number 1=A122008TR-ND, Voltage - Rated=30V
JP1: library part "JP 1x4 2.54 Cai Cong", "Cắm"
JP2: library part "JP 2x4 2.54 Cai Thang", "Cắm"
JP3 JP4: library part "JP 1x5 2.54 Duc Thang", "Cắm"
JP5: library part "JP 1x2 2.54 Cai Thang", "Cắm"
L1: library part SLF7032T-100M1R4-2PF, "FIXED IND 10UH 1.4A 63.6 MOHM", Current Rating (Amps)=1.4A, DC Resistance (DCR)="63.6mOhm Max", Device Package=Nonstandard, Inductance Frequency - Test=100kHz, Manufacturer="TDK Corporation", Operating Temperature="-40°C ~ 105°C", Supplier Part Number 1=445-1998-1-ND, Tolerance=±20%
P1: "Header, 14-Pin"
P2: "Micro SD Card Socket", Package=None
Q1: "N/A", Package=Package
R1 R2 R3 R5 R23 R24: library part RC0402FR-07680RL, "RES 680 OHM 1% 1/16W 0402", Device Package="0402 (1005 Metric)", Manufacturer=Yageo, Operating Temperature="-55°C ~ 155°C", Power (Watts)="0.063W, 1/16W", Supplier Device Package=0402, Supplier Part Number 1=311-680LRCT-ND, Temperature Coefficient=±100ppm/°C, Tolerance=±1%
R4: library part MCS04020D1003BE100, "RES SMD 100K OHM 0.1% 1/16W 0402", Device Package="0402 (1005 Metric)", Manufacturer="Vishay Beyschlag", Operating Temperature="-55°C ~ 125°C", Power (Watts)="0.063W, 1/16W", Supplier Device Package=0402, Supplier Part Number 1=749-1594-1-ND, Temperature Coefficient=±25ppm/°C, Tolerance=±0.1%
R6 R7: library part RP73PF1E10KBTD, "RES 10K OHM 0.1% 1/10W 0402", Device Package="0402 (1005 Metric)", Manufacturer="TE Connectivity Passive Product", Operating Temperature="-55°C ~ 155°C", Power (Watts)="0.1W, 1/10W", Supplier Device Package=0402, Supplier Part Number 1=A127415CT-ND, Temperature Coefficient=±25ppm/°C, Tolerance=±0.1%
R8 R11 R12 R13 R17 R18: library part RK73H1ERTTP4701F, "RES 4.7K OHM 1% 1/10W 0402", Device Package="0402 (1005 Metric)", Manufacturer="KOA Speer Electronics, Inc.", Operating Temperature="-55°C ~ 155°C", Power (Watts)="0.1W, 1/10W", Ratings=AEC-Q200, Supplier Device Package=0402, Supplier Part Number 1=2019-RK73H1ERTTP4701FCT-ND, Temperature Coefficient=±100ppm/°C, Tolerance=±1%
R9 R22: library part MCS0402MC1002FE000, "RES SMD 10K OHM 1% 1/10W 0402", Device Package="0402 (1005 Metric)", Manufacturer="Vishay Beyschlag", Operating Temperature="-55°C ~ 175°C", Power (Watts)="0.1W, 1/10W", Ratings=AEC-Q200, Supplier Device Package=0402, Supplier Part Number 1=MCS0402-10.0K-MFCT-ND, Temperature Coefficient=±50ppm/°C, Tolerance=±1%
R10: library part 3362P-1-103LF, "TRIMMER 10K OHM 0.5W PC PIN TOP", Manufacturer="Bourns Inc.", Power (Watts)="0.5W, 1/2W", Resistive Material=Cermet, Supplier Part Number 1=3362P-103LF-ND, Temperature Coefficient=±100ppm/°C, Tolerance=±10%
R14: library part CRT0603-FY-47R0ELF, "RES SMD 47 OHM 1% 1/10W 0603", Device Package="0603 (1608 Metric)", Manufacturer="Bourns Inc.", Operating Temperature="-55°C ~ 155°C", Power (Watts)="0.1W, 1/10W", Supplier Device Package=0603, Supplier Part Number 1=118-CRT0603-FY-47R0ELFCT-ND, Temperature Coefficient=±25ppm/°C, Tolerance=±1%
R15: library part RG1608P-203-B-T5, "RES SMD 20K OHM 0.1% 1/10W 0603", Device Package="0603 (1608 Metric)", Manufacturer=Susumu, Operating Temperature="-55°C ~ 155°C", Power (Watts)="0.1W, 1/10W", Ratings=AEC-Q200, Supplier Device Package=0603, Supplier Part Number 1=RG16P20.0KBCT-ND, Temperature Coefficient=±25ppm/°C, Tolerance=±0.1%
R16: library part CR0603AJ/-000ELF, "RES 0 OHM JUMPER 1/10W 0603", Device Package="0603 (1608 Metric)", Manufacturer="Bourns Inc.", Operating Temperature="-55°C ~ 155°C", Power (Watts)="0.1W, 1/10W", Ratings=AEC-Q200, Supplier Device Package=0603, Supplier Part Number 1=118-CR0603AJ/-000ELFCT-ND, Tolerance=Jumper
R19: library part ERJ-2RKF5232X, "RES SMD 52.3K OHM 1% 1/10W 0402", Device Package="0402 (1005 Metric)", Manufacturer="Panasonic Electronic Components", Operating Temperature="-55°C ~ 155°C", Power (Watts)="0.1W, 1/10W", Ratings=AEC-Q200, Supplier Device Package=0402, Supplier Part Number 1=P52.3KLCT-ND, Temperature Coefficient=±100ppm/°C, Tolerance=±1%
R20: library part RP73PF1E100KBTD, "RES 100K OHM 0.1% 1/10W 0402", Device Package="0402 (1005 Metric)", Manufacturer="TE Connectivity Passive Product", Operating Temperature="-55°C ~ 155°C", Power (Watts)="0.1W, 1/10W", Supplier Device Package=0402, Supplier Part Number 1=A127511CT-ND, Temperature Coefficient=±25ppm/°C, Tolerance=±0.1%
R21: library part MCS0402MC1001FE000, "RES SMD 1K OHM 1% 1/10W 0402", Device Package="0402 (1005 Metric)", Manufacturer="Vishay Beyschlag", Operating Temperature="-55°C ~ 175°C", Power (Watts)="0.1W, 1/10W", Ratings=AEC-Q200, Supplier Device Package=0402, Supplier Part Number 1=MCS0402-1.00K-MFCT-ND, Temperature Coefficient=±50ppm/°C, Tolerance=±1%
R25: library part ERJ-2RKF1201X, "RES SMD 1.2K OHM 1% 1/10W 0402", Device Package="0402 (1005 Metric)", Manufacturer="Panasonic Electronic Components", Operating Temperature="-55°C ~ 155°C", Power (Watts)="0.1W, 1/10W", Ratings=AEC-Q200, Supplier Device Package=0402, Supplier Part Number 1=P1.20KLCT-ND, Temperature Coefficient=±100ppm/°C, Tolerance=±1%
R26: library part RK73H1ERTTP1001F, "RES 1K OHM 1% 1/10W 0402", Device Package="0402 (1005 Metric)", Manufacturer="KOA Speer Electronics, Inc.", Operating Temperature="-55°C ~ 155°C", Power (Watts)="0.1W, 1/10W", Ratings=AEC-Q200, Supplier Device Package=0402, Supplier Part Number 1=2019-RK73H1ERTTP1001FCT-ND, Temperature Coefficient=±100ppm/°C, Tolerance=±1%
R27: library part RK73H1ETTP1100F, "RES 110 OHM 1% 1/10W 0402", Device Package="0402 (1005 Metric)", Manufacturer="KOA Speer Electronics, Inc.", Operating Temperature="-55°C ~ 155°C", Power (Watts)="0.1W, 1/10W", Ratings=AEC-Q200, Supplier Device Package=0402, Supplier Part Number 1=2019-RK73H1ETTP1100FCT-ND, Temperature Coefficient=±100ppm/°C, Tolerance=±1%
R28 R29: library part RK73G1ETTP1001D, "RES 1K OHM 0.5% 1/10W 0402", Device Package="0402 (1005 Metric)", Manufacturer="KOA Speer Electronics, Inc.", Operating Temperature="-55°C ~ 155°C", Power (Watts)="0.1W, 1/10W", Ratings=AEC-Q200, Supplier Device Package=0402, Supplier Part Number 1=2019-RK73G1ETTP1001DCT-ND, Temperature Coefficient=±50ppm/°C, Tolerance=±0.5%
S2: "Switch"
U: "Amplifier IC 2-Channel _Stereo_ Class D 16-SOP", Package="SOP-16 Diodes Inc."
U1: "ARMÂ® CortexÂ®-M4 STM32F4 Microcontroller IC 32-Bit Single-Core 168MHz 512KB (512K x 8) FLASH 100-LQFP (14x14)", Package="LQFP-100 STMicroelectronics"
U2: "Buck Switching Regulator IC Positive Adjustable 0.8V 1 Output 1A SOT-23-6 Thin, TSOT-23-6", Package="SOT-23 Texas Instruments"
U3 U4: "Linear Voltage Regulator IC 1 Output 250mA SOT-23-3", Package="SOT-23-3 Microchip"
U5: "Complete single cell Li-Ion battery with a constant current / constant voltage linear charger", Package=Package
U6: "17V Clamp 5A (8/20Âµs) Ipp Tvs Diode Surface Mount SOT-23-6", Package="SOT-23-6 STMicroelectronics"
U7: "One Cell Lithium-ion/Polymer Battery Protection IC", Package="SOT-23-6 Fortune Semiconductor"
Y1: library part NX5032GA-8.000M-STD-CSU-1, "CRYSTAL 8.0000MHZ 8PF SMD", ESR (Equivalent Series Resistance)="300 Ohms", Frequency Stability=±150ppm, Frequency Tolerance=±50ppm, Load Capacitance=8pF, Manufacturer="NDK America, Inc.", Operating Mode=Fundamental, Operating Temperature="-40°C ~ 150°C", Package / Case="2-SMD, No Lead", Ratings=AEC-Q200, Supplier Part Number 1=644-1132-1-ND

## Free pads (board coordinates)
  round 196.85 hole 125.98: 8(110,1760) 8(120,115) 8(2215,115) 8(2215,1760)

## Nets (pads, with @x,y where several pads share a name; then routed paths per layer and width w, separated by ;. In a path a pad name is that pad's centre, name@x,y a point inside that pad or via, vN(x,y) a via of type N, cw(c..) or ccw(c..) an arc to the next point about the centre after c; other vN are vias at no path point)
+5: C19.2 C22.2 C23.2 C26.2 C31.2 C32.2 C34.1 C35.1 C36.1 C37.1 D1.1 D16.1 D17.1 J2.A4 J2.A9 J2.B4 J2.B9 JP3.2 JP4.2 L1.2 P1.14 R19.2 R21.2 U3.3 U4.3 U5.4 U5.8 U6.5 U.4 U.5 U.6 U.12 U.13
+8.4: C21.2 R7.2 R20.2 U2.5
ADC_Pin: C29.2 R7.1 R15.2 U1.67
ADC_VR_ESC: C24.2 J1.2 U1.68
Audio_PWM: R8.2 U1.92
B+: C38.1 R27.2 U5.5
B-: C39.2 Q1.2 Q1.3 U7.6
BOOT0: R6.2 U1.94
CHRG_LED: R28.1 U5.7
CLK_SD: P2.5 U1.78
CS_SD: P2.2 R18.1 U1.81
DISPL_CS: P1.12 U1.35
DISPL_DC: P1.10 U1.37
DISPL_LED: P1.7 U1.64
DISPL_MOSI: P1.3 P1.9 U1.32
DISPL_RST: P1.11 U1.34
DISPL_SCK: P1.5 P1.8 U1.30
JOY1_X: JP3.3 U1.24
JOY1_Y: JP3.4 U1.25
JOY2_X: JP4.3 U1.26
JOY2_Y: JP4.4 U1.29
LED1: R1.1 U1.59
LED2: R2.1 U1.60
LED3: R3.1 U1.61
LED4: R5.1 U1.62
MISO_SD: P2.7 R12.1 U1.79
MOSI_SD: P2.3 R11.1 U1.80
NetC16_1: C16.1 R10.2
NetC16_2: C16.2 R9.1
NetC17_2: C17.2 R8.1 R10.3
NetC18_2: C18.2 U.8
NetC19_1: C19.1 R19.1 R22.2 U2.3
NetC20_1: C20.1 D2.2 L1.1 U2.6
NetC20_2: C20.2 D1.2 U2.1
NetC39_1: C39.1 R27.1 U7.5
NetD3_1: D3.1 R21.1
NetD10_1: D10.1 R1.2
NetD11_1: D11.1 R2.2
NetD12_1: D12.1 R3.2
NetD13_1: D13.1 R5.2
NetD14_1: D14.1 R23.1
NetD15_1: D15.1 R24.1
NetD16_2: D16.2 R29.1
NetD17_2: D17.2 R28.2
NetJ2_A6: J2.A6 J2.B6 U6.3
NetJ2_A7: J2.A7 J2.B7 U6.1
NetJP5_1: JP5.1 U.1
NetJP5_2: JP5.2 U.3
NetP2_1: P2.1 R17.1
NetP2_8: P2.8 R13.1
NetQ1_1: Q1.1 Q1.8
NetQ1_4: Q1.4 U7.1
NetQ1_5: Q1.5 U7.3
NetR9_2: R9.2 U.7
NetR20_1: R20.1 U2.4
NetR25_2: R25.2 U5.2
NetR26_1: R26.1 U7.2
NRST: C3.2 R4.1 S2.2 U1.14
OSC_IN: C5.2 U1.12 Y1.2
OSC_OUT: C4.2 U1.13 Y1.1
OUT-: C1.1 C2.1 C3.1 C4.1 C5.1 C6.1 C7.2 C8.1 C9.1 C10.1 C11.1 C12.1 C13.1 C14.1 C15.1 C17.1 C18.1 C21.1 C22.1 C23.1 C24.1 C25.2 C26.1 C27.2 C28.1 C29.1 C30.2 C31.1 C32.1 C33.1 C34.2 C35.2 C36.2 C37.2 C38.2 D2.1 D3.2 D4.1 D8.1 D9.1 D10.2 D11.2 D12.2 D13.2 D14.2 D15.2 J1.1 J2.A1 J2.A12 J2.B1 J2.B12 J2.S JP1.2 JP2.5 JP3.1 JP4.1 P1.13 P2.6 P2.G1 P2.G2 P2.G3 P2.G4 Q1.6 Q1.7 R6.1 R10.1 R15.1 R22.1 R25.1 R26.2 S2.1 U1.10 U1.20 U1.27 U1.74 U1.99 U2.2 U3.1 U4.1 U5.1 U5.3 U5.9 U6.2 U.2 U.11 U.15
RF_CE: JP2.6 U1.52
RF_CSN: JP2.3 U1.51
RF_MISO: JP2.8 U1.53
RF_MOSI: JP2.2 U1.54
RF_SCK: JP2.7 U1.47
STDBY_LED: R29.2 U5.6
SWCLK: JP1.3 U1.76
SWDIO: JP1.1 U1.72
TOUCH_CS: P1.4 U1.36
TOUCH_INT: P1.1 U1.33
TOUCH_MISO: P1.2 U1.31
USB_DM: U1.70 U6.6
USB_DP: U1.71 U6.4
VBAT: C15.2 R16.2 U1.6
VCAP_1: C1.2 U1.49
VCAP_2: C2.2 U1.73
VCCNRF: C25.1 C33.2 JP2.4 R24.2 U4.2
VDD1: C8.2 C9.2 C10.2 C11.2 C12.2 C13.2 C14.2 C28.2 D4.2 J1.3 JP1.4 P2.4 R4.2 R11.2 R12.2 R13.2 R14.1 R16.1 R17.2 R18.2 R23.2 U1.11 U1.19 U1.28 U1.50 U1.75 U1.100 U3.2
VDDA: C7.1 C30.1 U1.22
VREF+: C6.2 C27.1 R14.2 U1.21
pads on no net: D8.2 D9.2 J2.A2 J2.A3 J2.A5 J2.A8 J2.A10 J2.A11 J2.B2 J2.B3 J2.B5 J2.B8 J2.B10 J2.B11 J2.M JP2.1 JP3.5 JP4.5 P1.6 P2. P2.9 U1.1 U1.2 U1.3 U1.4 U1.5 U1.7 U1.8 U1.9 U1.15 U1.16 U1.17 U1.18 U1.23 U1.38 U1.39 U1.40 U1.41 U1.42 U1.43 U1.44 U1.45 U1.46 U1.48 U1.55 U1.56 U1.57 U1.58 U1.63 U1.65 U1.66 U1.69 U1.77 U1.82 U1.83 U1.84 U1.85 U1.86 U1.87 U1.88 U1.89 U1.90 U1.91 U1.93 U1.95 U1.96 U1.97 U1.98 U7.4 U.9 U.10 U.14 U.16

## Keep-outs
Keep-Out Layer:
  lines w10: 0,0 0,1880 2335,1880 2335,0 0,0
